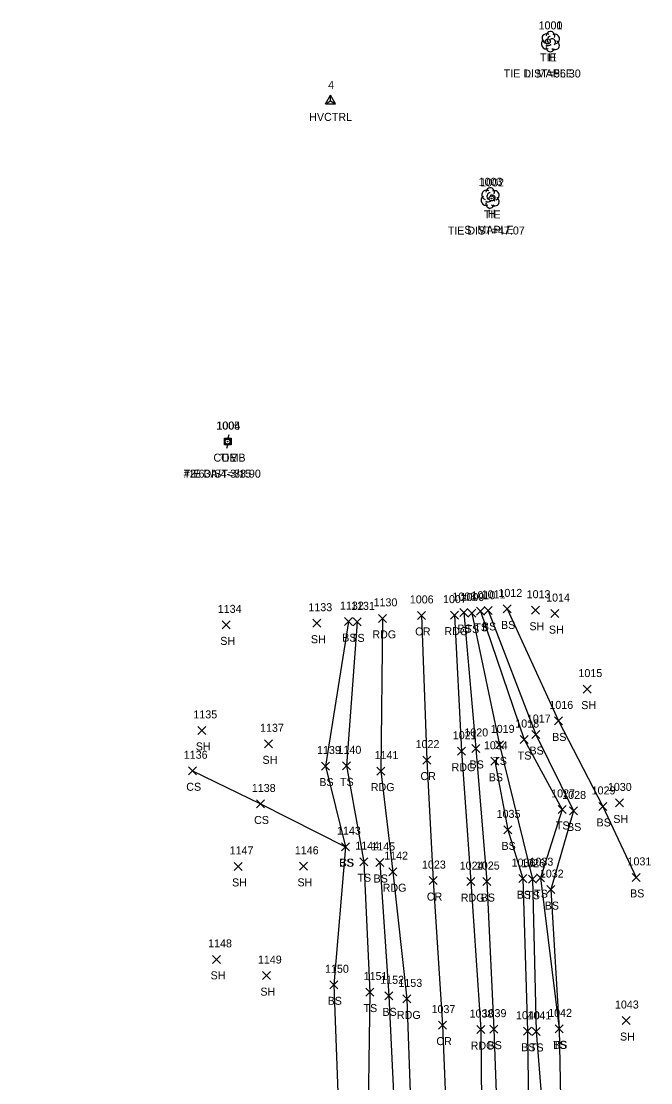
# Model space of a CAD drawing. Extents: x 1678553 to 1680768, y 787260 to 792325.
# Drawn here: x 1678598.8 to 1678756.1, y 787718.8 to 787983.9 of the extents above; entities that cross this region are included whole.
import ezdxf

# ---------------------------------------------------------------- set-up
doc = ezdxf.new("R2010")
doc.units = 0
for name, color, linetype in [('C_A', 7, 'Continuous'), ('C_C', 7, 'Continuous'), ('C_I', 7, 'Continuous'), ('CBP', 7, 'Continuous'), ('CPSM', 7, 'Continuous'), ('L_A', 7, 'Continuous'), ('L_C', 7, 'Continuous'), ('L_I', 7, 'Continuous'), ('L_TIC', 7, 'Continuous'), ('LELB', 7, 'Continuous'), ('LTD', 7, 'Continuous'), ('P_A', 7, 'Continuous'), ('P_I', 7, 'Continuous'), ('P_TIC', 7, 'Continuous'), ('PEU', 7, 'Continuous'), ('PRC', 7, 'Continuous'), ('U_A', 7, 'Continuous'), ('U_C', 7, 'Continuous'), ('U_I', 7, 'Continuous'), ('UP', 7, 'Continuous')]:
    doc.layers.add(name, color=color, linetype=linetype)

msp = doc.modelspace()

# ---------------------------------------------------------------- linework, layer by layer
at = {"layer": 'CBP'}
for centre, radius in [((1678730.39, 787978.89), 0.625), ((1678730.39, 787978.89), 0.0833), ((1678716.35, 787939.67), 0.625), ((1678716.35, 787939.67), 0.0833), ((1678650.38, 787878.94), 0.625), ((1678650.38, 787878.94), 0.0833)]:
    msp.add_circle(centre, radius, dxfattribs=at)
at = {"layer": 'CPSM'}
for p, q in [((1678674.82, 787963.33), (1678676.07, 787965.49)), ((1678677.32, 787963.33), (1678676.07, 787965.49)), ((1678676.07, 787964.05), (1678676.07, 787965.49)), ((1678674.82, 787963.33), (1678676.07, 787964.05)), ((1678674.82, 787963.33), (1678677.32, 787963.33)), ((1678676.07, 787964.05), (1678676.07, 787964.05)), ((1678676.07, 787964.05), (1678677.32, 787963.33))]:
    msp.add_line(p, q, dxfattribs=at)
at = {"layer": 'L_TIC'}
for points in [[(1678719.27, 787836.15), (1678721.27, 787838.15)], [(1678721.27, 787836.15), (1678719.27, 787838.15)], [(1678708.4, 787835.24), (1678710.4, 787837.24)], [(1678710.4, 787835.24), (1678708.4, 787837.24)], [(1678710.45, 787835.11), (1678712.45, 787837.11)], [(1678712.45, 787835.11), (1678710.45, 787837.11)], [(1678712.62, 787835.56), (1678714.62, 787837.56)], [(1678714.62, 787835.56), (1678712.62, 787837.56)], [(1678714.51, 787835.78), (1678716.51, 787837.78)], [(1678716.51, 787835.78), (1678714.51, 787837.78)], [(1678726.32, 787835.82), (1678728.32, 787837.82)], [(1678728.32, 787835.82), (1678726.32, 787837.82)], [(1678731.19, 787834.98), (1678733.19, 787836.98)], [(1678733.19, 787834.98), (1678731.19, 787836.98)], [(1678649.05, 787832.16), (1678651.05, 787834.16)], [(1678651.05, 787832.16), (1678649.05, 787834.16)], [(1678671.7, 787832.58), (1678673.7, 787834.58)], [(1678673.7, 787832.58), (1678671.7, 787834.58)], [(1678679.58, 787832.98), (1678681.58, 787834.98)], [(1678681.58, 787832.98), (1678679.58, 787834.98)], [(1678681.79, 787832.91), (1678683.79, 787834.91)], [(1678683.79, 787832.91), (1678681.79, 787834.91)], [(1678739.27, 787816.12), (1678741.27, 787818.12)], [(1678741.27, 787816.12), (1678739.27, 787818.12)], [(1678732.06, 787808.17), (1678734.06, 787810.17)], [(1678734.06, 787808.17), (1678732.06, 787810.17)], [(1678642.94, 787805.8), (1678644.94, 787807.8)], [(1678644.94, 787805.8), (1678642.94, 787807.8)], [(1678726.38, 787804.77), (1678728.38, 787806.77)], [(1678728.38, 787804.77), (1678726.38, 787806.77)], [(1678659.62, 787802.45), (1678661.62, 787804.45)], [(1678661.62, 787802.45), (1678659.62, 787804.45)], [(1678717.36, 787802.19), (1678719.36, 787804.19)], [(1678719.36, 787802.19), (1678717.36, 787804.19)], [(1678723.48, 787803.52), (1678725.48, 787805.52)], [(1678725.48, 787803.52), (1678723.48, 787805.52)], [(1678711.41, 787801.3), (1678713.41, 787803.3)], [(1678713.41, 787801.3), (1678711.41, 787803.3)], [(1678673.86, 787796.9), (1678675.86, 787798.9)], [(1678675.86, 787796.9), (1678673.86, 787798.9)], [(1678679.06, 787796.95), (1678681.06, 787798.95)], [(1678681.06, 787796.95), (1678679.06, 787798.95)], [(1678716.2, 787798.09), (1678718.2, 787800.09)], [(1678718.2, 787798.09), (1678716.2, 787800.09)], [(1678640.6, 787795.72), (1678642.6, 787797.72)], [(1678642.6, 787795.72), (1678640.6, 787797.72)], [(1678657.56, 787787.43), (1678659.56, 787789.43)], [(1678659.56, 787787.43), (1678657.56, 787789.43)], [(1678733.02, 787786.06), (1678735.02, 787788.06)], [(1678735.02, 787786.06), (1678733.02, 787788.06)], [(1678735.79, 787785.68), (1678737.79, 787787.68)], [(1678737.79, 787785.68), (1678735.79, 787787.68)], [(1678743.15, 787786.81), (1678745.15, 787788.81)], [(1678745.15, 787786.81), (1678743.15, 787788.81)], [(1678747.29, 787787.68), (1678749.29, 787789.68)], [(1678749.29, 787787.68), (1678747.29, 787789.68)], [(1678719.39, 787780.96), (1678721.39, 787782.96)], [(1678721.39, 787780.96), (1678719.39, 787782.96)], [(1678678.85, 787776.76), (1678680.85, 787778.76)], [(1678680.85, 787776.76), (1678678.85, 787778.76)], [(1678678.85, 787776.76), (1678680.85, 787778.76)], [(1678680.85, 787776.76), (1678678.85, 787778.76)], [(1678678.85, 787776.76), (1678680.85, 787778.76)], [(1678680.85, 787776.76), (1678678.85, 787778.76)], [(1678683.41, 787773.01), (1678685.41, 787775.01)], [(1678685.41, 787773.01), (1678683.41, 787775.01)], [(1678687.43, 787772.81), (1678689.43, 787774.81)], [(1678689.43, 787772.81), (1678687.43, 787774.81)], [(1678652, 787771.83), (1678654, 787773.83)], [(1678654, 787771.83), (1678652, 787773.83)], [(1678668.36, 787771.86), (1678670.36, 787773.86)], [(1678670.36, 787771.86), (1678668.36, 787773.86)], [(1678714.2, 787768.05), (1678716.2, 787770.05)], [(1678716.2, 787768.05), (1678714.2, 787770.05)], [(1678723.18, 787768.78), (1678725.18, 787770.78)], [(1678725.18, 787768.78), (1678723.18, 787770.78)], [(1678725.6, 787768.62), (1678727.6, 787770.62)], [(1678727.6, 787768.62), (1678725.6, 787770.62)], [(1678727.6, 787769.01), (1678729.6, 787771.01)], [(1678729.6, 787769.01), (1678727.6, 787771.01)], [(1678751.53, 787769.09), (1678753.53, 787771.09)], [(1678753.53, 787769.09), (1678751.53, 787771.09)], [(1678730.19, 787766.04), (1678732.19, 787768.04)], [(1678732.19, 787766.04), (1678730.19, 787768.04)], [(1678730.19, 787766.04), (1678732.19, 787768.04)], [(1678732.19, 787766.04), (1678730.19, 787768.04)], [(1678646.64, 787748.61), (1678648.64, 787750.61)], [(1678648.64, 787748.61), (1678646.64, 787750.61)], [(1678659.08, 787744.55), (1678661.08, 787746.55)], [(1678661.08, 787744.55), (1678659.08, 787746.55)], [(1678675.94, 787742.26), (1678677.94, 787744.26)], [(1678677.94, 787742.26), (1678675.94, 787744.26)], [(1678684.93, 787740.44), (1678686.93, 787742.44)], [(1678686.93, 787740.44), (1678684.93, 787742.44)], [(1678689.64, 787739.5), (1678691.64, 787741.5)], [(1678691.64, 787739.5), (1678689.64, 787741.5)], [(1678748.96, 787733.33), (1678750.96, 787735.33)], [(1678750.96, 787733.33), (1678748.96, 787735.33)], [(1678715.9, 787731.18), (1678717.9, 787733.18)], [(1678717.9, 787731.18), (1678715.9, 787733.18)], [(1678724.32, 787730.66), (1678726.32, 787732.66)], [(1678726.32, 787730.66), (1678724.32, 787732.66)], [(1678726.53, 787730.61), (1678728.53, 787732.61)], [(1678728.53, 787730.61), (1678726.53, 787732.61)], [(1678732.28, 787731.25), (1678734.28, 787733.25)], [(1678734.28, 787731.25), (1678732.28, 787733.25)], [(1678732.28, 787731.25), (1678734.28, 787733.25)], [(1678734.28, 787731.25), (1678732.28, 787733.25)]]:
    msp.add_lwpolyline(points, dxfattribs=at)
at = {"layer": 'LELB'}
for points in [[(1678709.4, 787836.24), (1678712.41, 787802.3), (1678715.2, 787769.05), (1678716.9, 787732.18), (1678717.88, 787705.06), (1678718.28, 787671.33), (1678717.39, 787651.57), (1678716.82, 787637.9), (1678725.59, 787615.48)], [(1678711.45, 787836.11), (1678718.36, 787803.19), (1678726.6, 787769.62), (1678727.53, 787731.61), (1678729.61, 787705.71), (1678731.13, 787671.96), (1678730.51, 787662.19), (1678730, 787652.74), (1678734.05, 787644.53), (1678725.82, 787633.71), (1678728.53, 787616.43)], [(1678713.62, 787836.56), (1678724.48, 787804.52), (1678734.02, 787787.06), (1678728.6, 787770.01), (1678733.28, 787732.25)], [(1678715.51, 787836.78), (1678727.38, 787805.77), (1678736.79, 787786.68), (1678731.19, 787767.04)], [(1678720.27, 787837.15), (1678733.06, 787809.17), (1678744.15, 787787.81), (1678752.53, 787770.09)], [(1678682.79, 787833.91), (1678680.06, 787797.95), (1678684.41, 787774.01), (1678685.93, 787741.44), (1678685.35, 787700.95), (1678687.11, 787668.14), (1678687.2, 787641.08), (1678680.87, 787618.81), (1678668.88, 787598.73), (1678664.34, 787597.34), (1678649.24, 787605.39), (1678627.9, 787609.82), (1678598.79, 787611.78)], [(1678680.58, 787833.98), (1678674.86, 787797.9), (1678679.85, 787777.76)], [(1678717.2, 787799.09), (1678720.39, 787781.96), (1678724.18, 787769.78), (1678725.32, 787731.66), (1678725.65, 787705.9), (1678725.04, 787671.33), (1678725.3, 787652.23)], [(1678641.6, 787796.72), (1678658.56, 787788.43), (1678679.85, 787777.76)], [(1678679.85, 787777.76), (1678676.94, 787743.26), (1678678.47, 787700.71), (1678682.02, 787669.14), (1678678.15, 787641.14), (1678680.87, 787618.81)], [(1678688.43, 787773.81), (1678690.64, 787740.5), (1678692.52, 787702.31), (1678693.52, 787666.89), (1678691.12, 787642.36), (1678682.92, 787618.46), (1678670.44, 787597.06), (1678663.82, 787591.2)], [(1678731.19, 787767.04), (1678733.28, 787732.25), (1678733.74, 787706.51), (1678734.64, 787672.29)]]:
    msp.add_lwpolyline(points, dxfattribs=at)
at = {"layer": 'LTD'}
for p, q in [((1678731.04, 787978.91), (1678731.04, 787978.91)), ((1678731.04, 787978.91), (1678731.04, 787978.91)), ((1678715.97, 787939.85), (1678715.97, 787939.85)), ((1678715.97, 787939.85), (1678715.97, 787939.85))]:
    msp.add_line(p, q, dxfattribs=at)
for centre in [(1678731.09, 787980.35), (1678716.01, 787941.29)]:
    msp.add_arc(centre, 1.05, 335.5272, 180.9563, dxfattribs=at)
for centre, major_axis, ratio, start_param, end_param in [((1678729.96, 787978.21), (0.58, -1.04), 0.959034, 3.141593, 6.283185), ((1678730.25, 787979.58), (1.21, -0.51), 0.895232, 1.570796, 4.712389), ((1678730.83, 787979.37), (-0.208, -0.792), 0.645439, 3.141593, 6.283185), ((1678731.54, 787978.75), (-0.5, 0.667), 0.989748, 3.141593, 6.283185), ((1678732.04, 787978.08), (-1.09, 0.79), 0.841452, 1.570796, 4.712389), ((1678732.08, 787979.5), (-1.14, -0.48), 0.949671, 1.570796, 4.712389), ((1678731.04, 787977.41), (0.26, 1.06), 0.942809, 1.570796, 4.712389), ((1678730.58, 787978.16), (-0.625, -0.083), 0.423636, 0, 3.141593), ((1678715.18, 787940.52), (1.21, -0.51), 0.895232, 1.570796, 4.712389), ((1678717.01, 787940.44), (-1.14, -0.48), 0.949671, 1.570796, 4.712389), ((1678714.88, 787939.14), (0.58, -1.04), 0.959034, 3.141593, 6.283185), ((1678715.51, 787939.1), (-0.625, -0.083), 0.423636, 0, 3.141593), ((1678715.76, 787940.31), (-0.208, -0.792), 0.645439, 3.141593, 6.283185), ((1678716.47, 787939.69), (-0.5, 0.667), 0.989748, 3.141593, 6.283185), ((1678716.97, 787939.02), (-1.09, 0.79), 0.841452, 1.570796, 4.712389), ((1678715.97, 787938.35), (0.26, 1.06), 0.942809, 1.570796, 4.712389)]:
    msp.add_ellipse(centre, major_axis=major_axis, ratio=ratio, start_param=start_param, end_param=end_param, dxfattribs=at)
at = {"layer": 'P_TIC'}
for points in [[(1678688.06, 787833.79), (1678690.06, 787835.79)], [(1678690.06, 787833.79), (1678688.06, 787835.79)], [(1678697.82, 787834.52), (1678699.82, 787836.52)], [(1678699.82, 787834.52), (1678697.82, 787836.52)], [(1678706.07, 787834.6), (1678708.07, 787836.6)], [(1678708.07, 787834.6), (1678706.07, 787836.6)], [(1678707.87, 787800.61), (1678709.87, 787802.61)], [(1678709.87, 787800.61), (1678707.87, 787802.61)], [(1678699.15, 787798.39), (1678701.15, 787800.39)], [(1678701.15, 787798.39), (1678699.15, 787800.39)], [(1678687.67, 787795.64), (1678689.67, 787797.64)], [(1678689.67, 787795.64), (1678687.67, 787797.64)], [(1678690.65, 787770.51), (1678692.65, 787772.51)], [(1678692.65, 787770.51), (1678690.65, 787772.51)], [(1678700.73, 787768.29), (1678702.73, 787770.29)], [(1678702.73, 787768.29), (1678700.73, 787770.29)], [(1678710.16, 787768.03), (1678712.16, 787770.03)], [(1678712.16, 787768.03), (1678710.16, 787770.03)], [(1678694.2, 787738.73), (1678696.2, 787740.73)], [(1678696.2, 787738.73), (1678694.2, 787740.73)], [(1678703.12, 787732.19), (1678705.12, 787734.19)], [(1678705.12, 787732.19), (1678703.12, 787734.19)], [(1678712.63, 787731.08), (1678714.63, 787733.08)], [(1678714.63, 787731.08), (1678712.63, 787733.08)]]:
    msp.add_lwpolyline(points, dxfattribs=at)
at = {"layer": 'PEU'}
for points in [[(1678707.07, 787835.6), (1678708.87, 787801.61), (1678711.16, 787769.03), (1678713.63, 787732.08), (1678713.93, 787704.33), (1678716.28, 787671.41), (1678712.68, 787651.27), (1678711.57, 787636.62), (1678710.35, 787611.37), (1678708.98, 787582.71), (1678707.82, 787563.26), (1678700.14, 787562.55), (1678691.17, 787560.92)], [(1678689.06, 787834.79), (1678688.67, 787796.64), (1678691.65, 787771.51), (1678695.2, 787739.73), (1678696.51, 787702.35), (1678697.46, 787665.85), (1678696.68, 787633.81), (1678695.1, 787616.53), (1678694.51, 787594.4), (1678691.17, 787560.92)]]:
    msp.add_lwpolyline(points, dxfattribs=at)
at = {"layer": 'PRC'}
msp.add_lwpolyline([(1678698.82, 787835.52), (1678700.15, 787799.39), (1678701.73, 787769.29), (1678704.12, 787733.19), (1678705.32, 787702.81), (1678705.89, 787671.87), (1678706.04, 787650.6), (1678702.84, 787611.29), (1678700.91, 787580.88), (1678700.14, 787562.55)], dxfattribs=at)
at = {"layer": 'UP'}
for p, q in [((1678650.71, 787880.6), (1678650.46, 787879.77)), ((1678649.62, 787878.1), (1678649.62, 787879.77)), ((1678649.62, 787879.77), (1678651.29, 787879.77)), ((1678651.29, 787878.1), (1678649.62, 787878.1)), ((1678650.21, 787877.27), (1678650.46, 787878.1)), ((1678650.46, 787878.94), (1678650.46, 787878.94)), ((1678651.29, 787879.77), (1678651.29, 787878.1))]:
    msp.add_line(p, q, dxfattribs=at)
msp.add_circle((1678650.46, 787878.94), 0.833, dxfattribs=at)

# ---------------------------------------------------------------- texts
at = {"layer": 'C_A'}
for s, p in [('TIE', (1678728.47, 787973.89)), ('HVCTRL', (1678670.77, 787959.05)), ('TIE', (1678714.43, 787934.67)), ('TIE', (1678648.46, 787873.94))]:
    msp.add_text(s, height=2, dxfattribs=at).set_placement(p)
at = {"layer": 'C_C'}
for s, p in [('TIE DIST=56.30', (1678719.39, 787969.89)), ('TIE DIST=47.07', (1678705.4, 787930.67)), ('TIE DIST=88.90', (1678639.43, 787869.94))]:
    msp.add_text(s, height=2, dxfattribs=at).set_placement(p)
at = {"layer": 'C_I'}
for s, p in [('1001', (1678728.11, 787981.89)), ('4', (1678675.51, 787967.05)), ('1002', (1678713.5, 787942.67)), ('1005', (1678647.53, 787881.94))]:
    msp.add_text(s, height=2, dxfattribs=at).set_placement(p)
at = {"layer": 'L_A'}
for s, p in [('H', (1678730.48, 787973.91)), ('H', (1678715.4, 787934.85)), ('BS', (1678707.84, 787831.24)), ('TS', (1678709.86, 787831.11)), ('TS', (1678712.03, 787831.56)), ('BS', (1678713.95, 787831.78)), ('BS', (1678718.71, 787832.15)), ('SH', (1678725.81, 787831.82)), ('SH', (1678730.68, 787830.98)), ('SH', (1678648.54, 787828.16)), ('SH', (1678671.19, 787828.58)), ('BS', (1678679.02, 787828.98)), ('TS', (1678681.2, 787828.91)), ('SH', (1678738.76, 787812.12)), ('SH', (1678642.43, 787801.8)), ('BS', (1678731.5, 787804.17)), ('TS', (1678722.89, 787799.52)), ('BS', (1678725.82, 787800.77)), ('SH', (1678659.1, 787798.45)), ('BS', (1678710.85, 787797.3)), ('TS', (1678716.77, 787798.19)), ('BS', (1678715.64, 787794.09)), ('CS', (1678640.04, 787791.72)), ('BS', (1678673.3, 787792.9)), ('TS', (1678678.47, 787792.95)), ('CS', (1678657, 787783.43)), ('SH', (1678746.78, 787783.68)), ('TS', (1678732.43, 787782.06)), ('BS', (1678735.23, 787781.68)), ('BS', (1678742.59, 787782.81)), ('BS', (1678718.83, 787776.96)), ('CS', (1678678.29, 787772.76)), ('BS', (1678678.29, 787772.76)), ('BS', (1678678.29, 787772.76)), ('SH', (1678651.49, 787767.83)), ('SH', (1678667.84, 787767.86)), ('TS', (1678682.82, 787769.01)), ('BS', (1678686.87, 787768.81)), ('BS', (1678722.62, 787764.78)), ('TS', (1678725.01, 787764.62)), ('TS', (1678727.01, 787765.01)), ('BS', (1678750.97, 787765.09)), ('BS', (1678713.64, 787764.05)), ('BS', (1678729.63, 787762.04)), ('BS', (1678729.63, 787762.04)), ('SH', (1678646.12, 787744.61)), ('SH', (1678658.57, 787740.55)), ('BS', (1678675.38, 787738.26)), ('TS', (1678684.34, 787736.44)), ('BS', (1678689.08, 787735.5)), ('SH', (1678748.45, 787729.33)), ('BS', (1678715.34, 787727.18)), ('BS', (1678723.76, 787726.66)), ('TS', (1678725.94, 787726.61)), ('TS', (1678731.69, 787727.25)), ('BS', (1678731.72, 787727.25))]:
    msp.add_text(s, height=2, dxfattribs=at).set_placement(p)
at = {"layer": 'L_C'}
for s, p in [('L. MAPLE', (1678724.66, 787969.91)), ('S. MAPLE', (1678709.54, 787930.85))]:
    msp.add_text(s, height=2, dxfattribs=at).set_placement(p)
at = {"layer": 'L_I'}
for s, p in [('1000', (1678728.11, 787981.91)), ('1003', (1678713.12, 787942.85)), ('1008', (1678706.55, 787839.24)), ('1009', (1678708.59, 787839.11)), ('1010', (1678711.32, 787839.56)), ('1011', (1678713.87, 787839.78)), ('1012', (1678718.07, 787840.15)), ('1013', (1678725.12, 787839.82)), ('1014', (1678729.99, 787838.98)), ('1134', (1678647.92, 787836.16)), ('1133', (1678670.57, 787836.58)), ('1132', (1678678.45, 787836.98)), ('1131', (1678681.23, 787836.91)), ('1015', (1678738.07, 787820.12)), ('1016', (1678730.8, 787812.17)), ('1135', (1678641.82, 787809.8)), ('1018', (1678722.28, 787807.52)), ('1017', (1678725.17, 787808.77)), ('1137', (1678658.49, 787806.45)), ('1020', (1678709.55, 787805.3)), ('1019', (1678716.15, 787806.19)), ('1034', (1678714.43, 787802.09)), ('1136', (1678639.42, 787799.72)), ('1139', (1678672.73, 787800.9)), ('1140', (1678677.85, 787800.95)), ('1138', (1678656.43, 787791.43)), ('1030', (1678745.43, 787791.68)), ('1027', (1678731.25, 787790.06)), ('1028', (1678734.02, 787789.68)), ('1029', (1678741.37, 787790.81)), ('1035', (1678717.62, 787784.96)), ('1143', (1678677.72, 787780.76)), ('1143', (1678677.72, 787780.76)), ('1143', (1678677.72, 787780.76)), ('1147', (1678650.88, 787775.83)), ('1146', (1678667.18, 787775.86)), ('1144', (1678682.29, 787777.01)), ('1145', (1678686.3, 787776.81)), ('1036', (1678721.35, 787772.78)), ('1026', (1678723.78, 787772.62)), ('1033', (1678725.83, 787773.01)), ('1031', (1678750.33, 787773.09)), ('1025', (1678712.43, 787772.05)), ('1032', (1678728.42, 787770.04)), ('1032', (1678728.42, 787770.04)), ('1148', (1678645.51, 787752.61)), ('1149', (1678657.95, 787748.55)), ('1150', (1678674.73, 787746.26)), ('1151', (1678684.37, 787744.44)), ('1152', (1678688.52, 787743.5)), ('1042', (1678730.51, 787735.25)), ('1042', (1678730.51, 787735.25)), ('1043', (1678747.19, 787737.33)), ('1039', (1678714.12, 787735.18)), ('1040', (1678722.46, 787734.66)), ('1041', (1678725.33, 787734.61))]:
    msp.add_text(s, height=2, dxfattribs=at).set_placement(p)
at = {"layer": 'P_A'}
for s, p in [('RDG', (1678686.55, 787829.79)), ('CR', (1678697.25, 787830.52)), ('RDG', (1678704.56, 787830.6)), ('RDG', (1678706.36, 787796.61)), ('CR', (1678698.58, 787794.39)), ('RDG', (1678686.16, 787791.64)), ('RDG', (1678689.13, 787766.51)), ('CR', (1678700.17, 787764.29)), ('RDG', (1678708.65, 787764.03)), ('RDG', (1678692.69, 787734.73)), ('CR', (1678702.55, 787728.19)), ('RDG', (1678711.12, 787727.08))]:
    msp.add_text(s, height=2, dxfattribs=at).set_placement(p)
at = {"layer": 'P_I'}
for s, p in [('1130', (1678686.85, 787837.79)), ('1006', (1678695.92, 787838.52)), ('1007', (1678704.22, 787838.6)), ('1021', (1678706.66, 787804.61)), ('1022', (1678697.37, 787802.39)), ('1141', (1678687.11, 787799.64)), ('1142', (1678689.52, 787774.51)), ('1023', (1678698.96, 787772.29)), ('1024', (1678708.39, 787772.03)), ('1153', (1678693.07, 787742.73)), ('1037', (1678701.35, 787736.19)), ('1038', (1678710.86, 787735.08))]:
    msp.add_text(s, height=2, dxfattribs=at).set_placement(p)
at = {"layer": 'U_A'}
msp.add_text('COMB', height=2, dxfattribs=at).set_placement((1678646.84, 787873.94))
at = {"layer": 'U_C'}
msp.add_text('#2/63A/4-3/15', height=2, dxfattribs=at).set_placement((1678639.4, 787869.94))
at = {"layer": 'U_I'}
msp.add_text('1004', height=2, dxfattribs=at).set_placement((1678647.61, 787881.94))

doc.saveas('drawing.dxf')
